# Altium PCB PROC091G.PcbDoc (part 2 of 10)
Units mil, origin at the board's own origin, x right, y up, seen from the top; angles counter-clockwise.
Board outline 4538.11 x 994.94 mil, 8 copper layers (Top Layer, GND1, Sig1, PWR1, PWR2, Sig2, GND2, Bottom Layer), stack 59.155 mil thick; 446 components, 329 nets, 5050 pads, 868 vias.
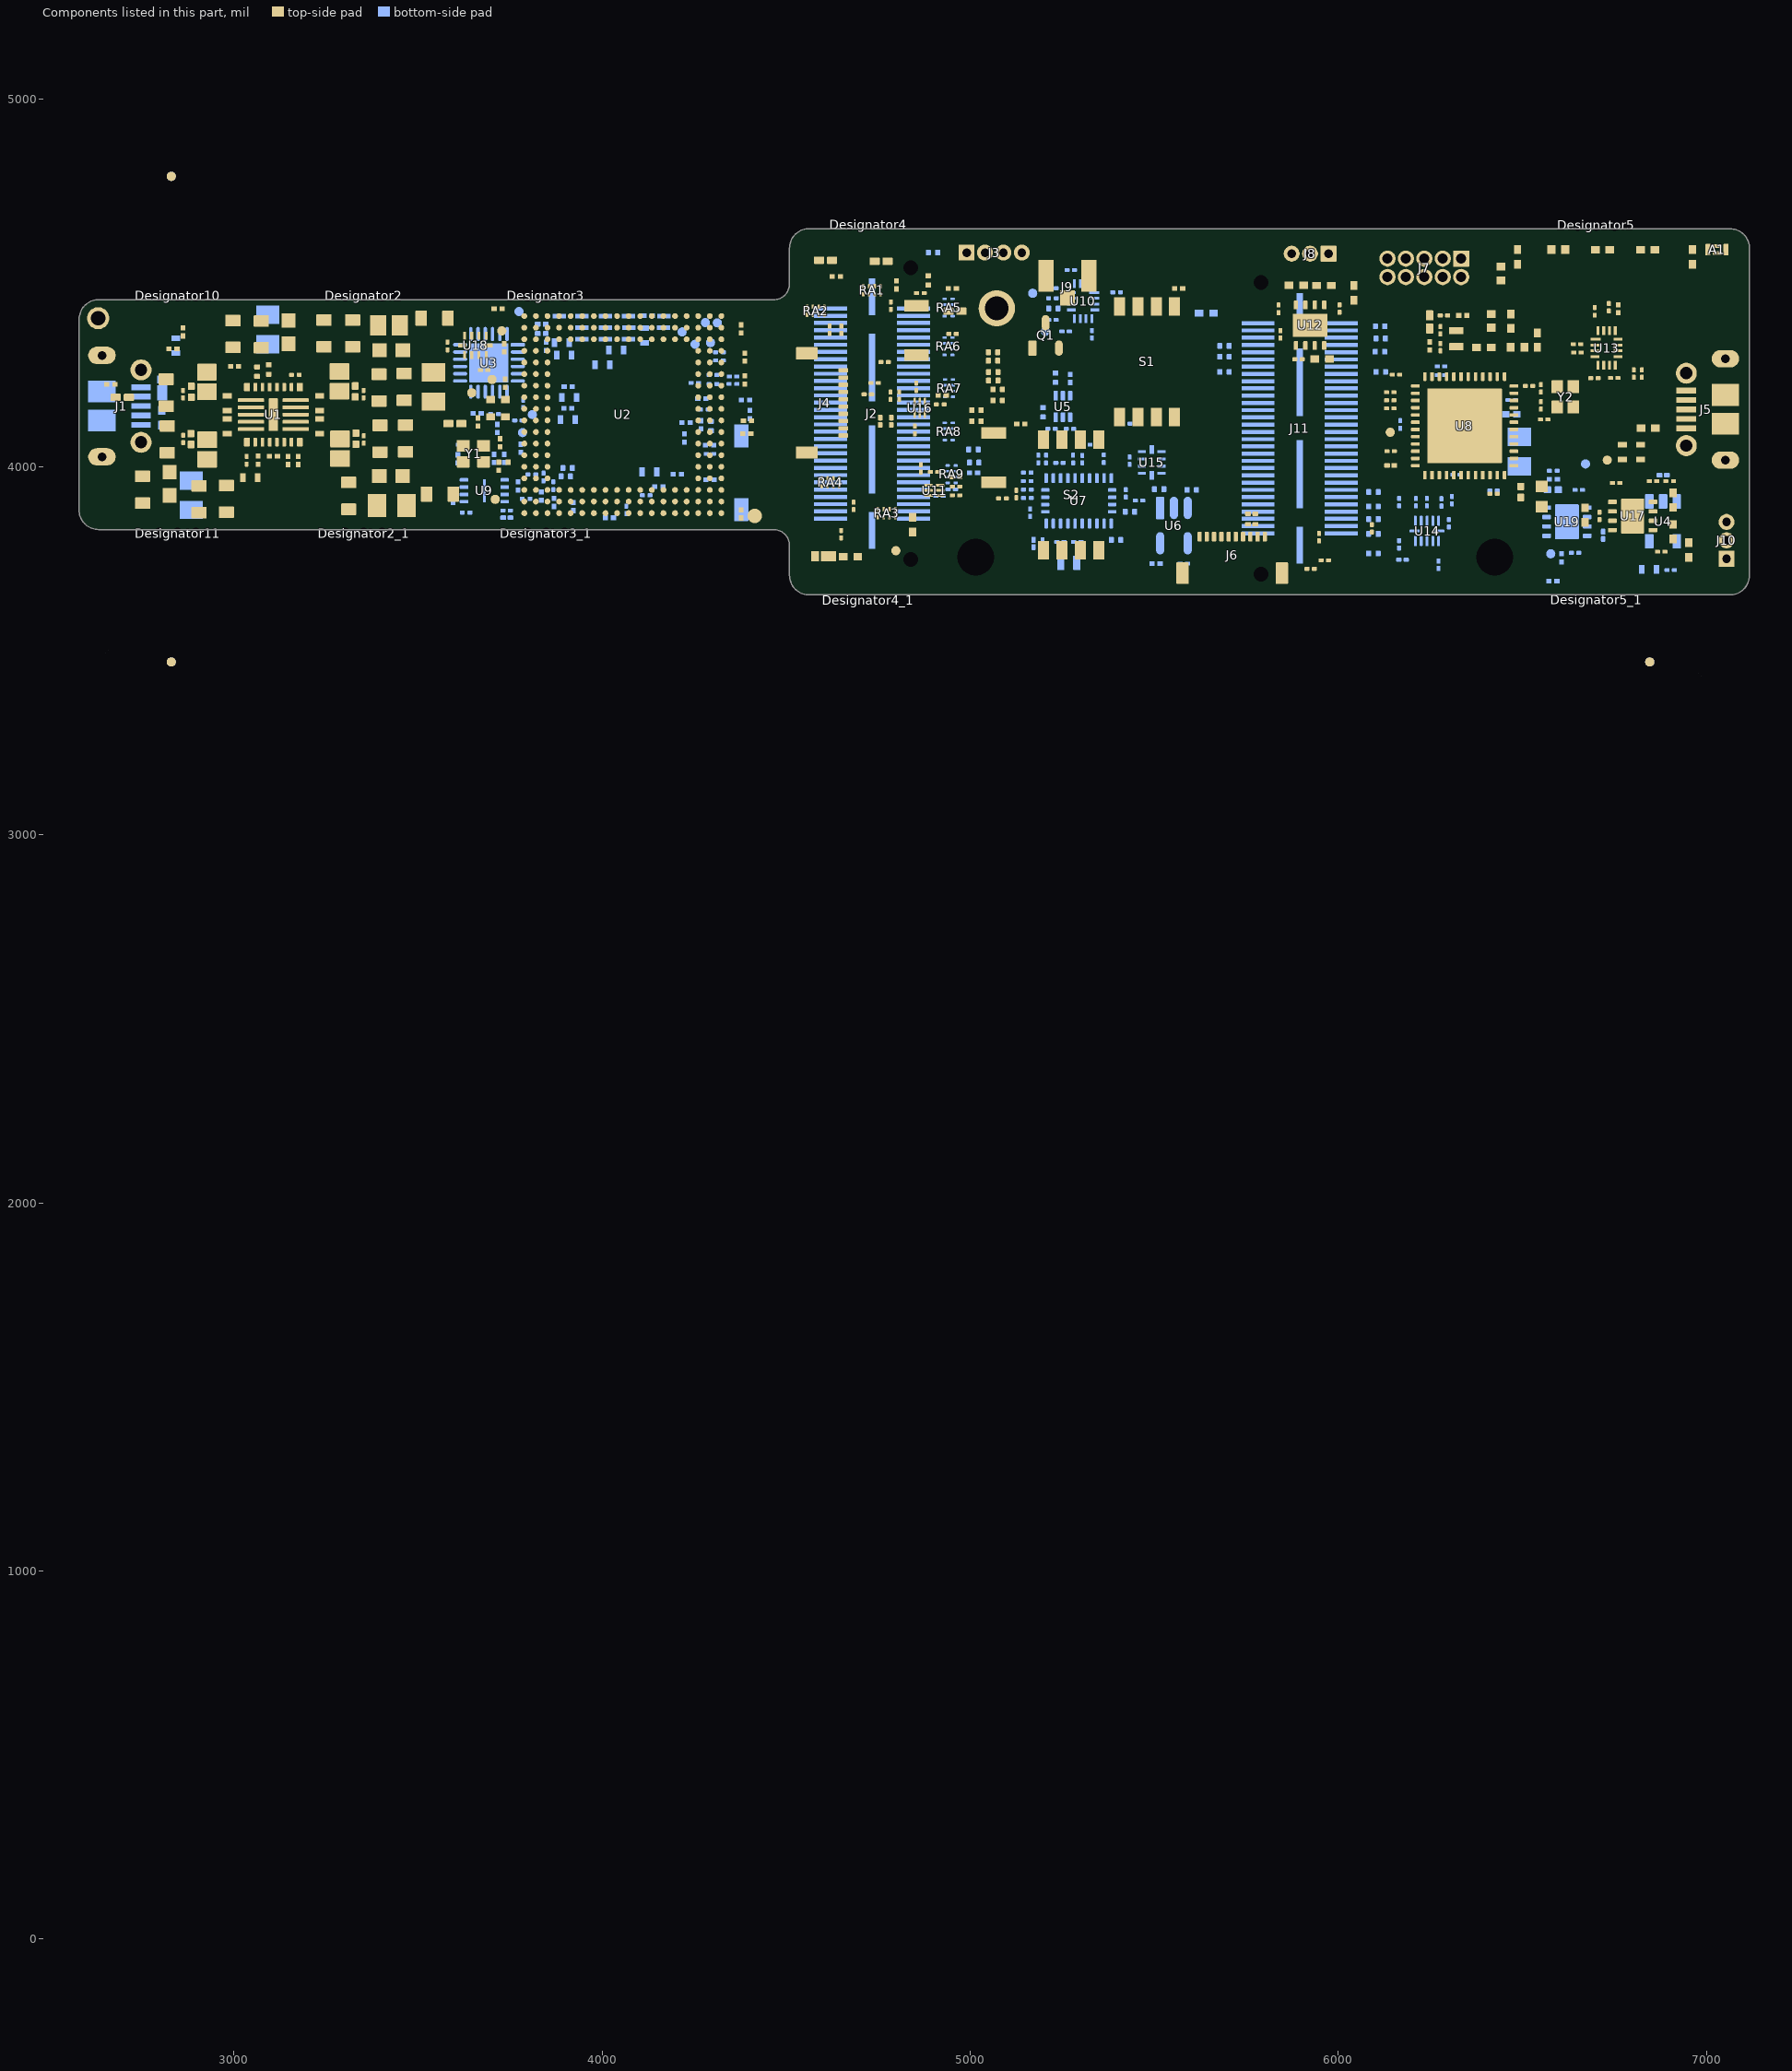
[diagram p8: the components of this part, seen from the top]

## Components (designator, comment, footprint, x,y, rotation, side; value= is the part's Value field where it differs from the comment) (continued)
R140 "AC0201FR-0720RL" FP-AC0201FR-0720RL_0201-IPC_C 4683.56,3893.44 r90 top
R141 "RC0201FR-074K99L" 0201L 6760.03,4429.26 r90 top value=4.99k
R142 "RC0201JR-070RL" "FP-RC0201JR-070RL_0201 (0603 Metric)-MFG" 5017.08,4123.69 r0 top
R143 "RC0201JR-070RL" "FP-RC0201JR-070RL_0201 (0603 Metric)-MFG" 5017.08,4153.69 r0 top
R144 "RC0201JR-070RL" "FP-RC0201JR-070RL_0201 (0603 Metric)-MFG" 5074.94,4180.12 r0 top
R145 "RC0201JR-070RL" "FP-RC0201JR-070RL_0201 (0603 Metric)-MFG" 5074.94,4210.12 r0 top
R146 "RC0201JR-070RL" "FP-RC0201JR-070RL_0201 (0603 Metric)-MFG" 5062.8,4234.19 r0 top
R147 "RC0201JR-070RL" "FP-RC0201JR-070RL_0201 (0603 Metric)-MFG" 5062.8,4257.19 r0 top
R148 "RC0201JR-070RL" "FP-RC0201JR-070RL_0201 (0603 Metric)-MFG" 5062.1,4288.03 r0 top
R149 "RC0201JR-070RL" "FP-RC0201JR-070RL_0201 (0603 Metric)-MFG" 5062.1,4311.03 r0 top
R150 "RC0201JR-070RL" "FP-RC0201JR-070RL_0201 (0603 Metric)-MFG" 6113.61,4381.76 r0 bottom
R151 "RC0201JR-070RL" "FP-RC0201JR-070RL_0201 (0603 Metric)-MFG" 6115.41,4348.48 r0 bottom
R152 "RC0201JR-070RL" "FP-RC0201JR-070RL_0201 (0603 Metric)-MFG" 5690.93,4328.4 r0 bottom
R153 "RC0201JR-070RL" "FP-RC0201JR-070RL_0201 (0603 Metric)-MFG" 6113.32,4312.59 r0 bottom
R154 "RC0201JR-070RL" "FP-RC0201JR-070RL_0201 (0603 Metric)-MFG" 5690.93,4298.93 r0 bottom
R155 "RC0201JR-070RL" "FP-RC0201JR-070RL_0201 (0603 Metric)-MFG" 6115.55,4257.57 r0 bottom
R157 "RC0201JR-070RL" "FP-RC0201JR-070RL_0201 (0603 Metric)-MFG" 5690.93,4257.72 r0 bottom
R158 "RC0201FR-0782K5L" 0201L 4228.2,4119.6 r0 bottom value=82.5k
R159 "RC0201JR-07750RL" 0201L 4223.5,4078.1 r270 bottom value=750
R160 "RC0201JR-070RL" "FP-RC0201JR-070RL_0201 (0603 METRIC)-IPC_C" 6280.34,3903.27 r90 bottom
R161 "RC0201JR-070RL" "FP-RC0201JR-070RL_0201 (0603 METRIC)-IPC_C" 6141.18,4158.46 r0 top
R166 "RC0201JR-070RL" "FP-RC0201JR-070RL_0201 (0603 METRIC)-IPC_C" 6240.62,3903.59 r90 bottom
R168 "RC0201JR-070RL" "FP-RC0201JR-070RL_0201 (0603 METRIC)-IPC_C" 6165.24,3903.57 r90 bottom
R170 "RC0201FR-0782K5L" 0201L 4154.35,3946.46 r180 bottom value=82.5k
R171 "RC0201JR-07750RL" 0201L 4204.44,3980.18 r0 bottom value=750
R172 "RC0201FR-0782K5L" 0201L 4401.11,4142.03 r90 bottom value=82.5k
R174 "RC0201FR-077K87L" 0201L 4269.1,4113.8 r90 bottom value=7.87k
R176 "RC0201FR-077K87L" 0201L 4389.6,4181.8 r0 bottom value=7.87k
R177 "RR0306P-103-D" FP-RR0306P-103-D_0201-IPC_C#1 4849.59,4099.95 r90 top
R178 "RR0306P-103-D" FP-RR0306P-103-D_0201-IPC_C#1 4918.69,4169.46 r180 top
R180 "ERJ-1GNF4701C" FP-ERJ-1GNF4701C_0201-IPC_C 6165.19,3789.15 r270 bottom
R181 "ERJ-1GNF4701C" FP-ERJ-1GNF4701C_0201-IPC_C 6091.28,3832.56 r90 top
R182 "RC0201JR-070RL" "FP-RC0201JR-070RL_0201 (0603 METRIC)-IPC_C" 4650.14,4371.83 r270 top locked
R183 "RC0201JR-070RL" "FP-RC0201JR-070RL_0201 (0603 METRIC)-IPC_C" 5947.68,3808.42 r270 top
R184 "RC0201JR-070RL" "FP-RC0201JR-070RL_0201 (0603 METRIC)-IPC_C" 5963.36,3745.98 r0 top
R185 "RC0201JR-070RL" "FP-RC0201JR-070RL_0201 (0603 METRIC)-IPC_C" 5925.33,3722.49 r180 top
R186 "RC0201JR-070RL" "FP-RC0201JR-070RL_0201 (0603 Metric)-MFG" 6095.54,3931.22 r0 bottom
R187 "RC0201JR-070RL" "FP-RC0201JR-070RL_0201 (0603 Metric)-MFG" 6095.54,3892.26 r0 bottom
R188 "RC0201JR-070RL" "FP-RC0201JR-070RL_0201 (0603 Metric)-MFG" 6095.54,3857.41 r0 bottom
R189 "RC0201JR-070RL" "FP-RC0201JR-070RL_0201 (0603 Metric)-MFG" 6095.54,3817.56 r0 bottom
R190 "RC0201JR-070RL" "FP-RC0201JR-070RL_0201 (0603 Metric)-MFG" 6095.54,3764.53 r0 bottom
RA1 "EXB-18VR000X" FP-EXB-18VR000X_0502-MFG 4733.17,4479.49 r180 top locked
RA2 "EXB-18VR000X" FP-EXB-18VR000X_0502-MFG 4580.6,4423.99 r180 top locked
RA3 "EXB-18VR000X" FP-EXB-18VR000X_0502-MFG 4772.94,3873.84 r0 top locked
RA4 "EXB-18VR000X" FP-EXB-18VR000X_0502-MFG 4620.57,3957.49 r0 top locked
RA5 "EXB-18VR000X" FP-EXB-18VR000X_0502-MFG 4941.51,4432.71 r90 bottom locked
RA6 "EXB-18VR000X" FP-EXB-18VR000X_0502-MFG 4941.09,4327.39 r90 bottom locked
RA7 "EXB-18VR000X" FP-EXB-18VR000X_0502-MFG 4942.52,4213.65 r90 bottom locked
RA8 "EXB-18VR000X" FP-EXB-18VR000X_0502-MFG 4941.86,4095.87 r90 bottom locked
RA9 "EXB-18VR000X" FP-EXB-18VR000X_0502-MFG 4949.85,3979.76 r90 bottom locked
S1 "218-4LPST" SW_218-4LPST 5480.37,4285.46 r90 top
S2 "218-4LPST" SW_218-4LPST 5274.37,3923.46 r90 top locked
S3 "CHS-01TA" FP-CHS-01TA_SMT_SW_5MM4_2MM5-MFG 4378.13,3983.7 r270 bottom
SW2 "B3U-1000P" SW_B3U-1000P 4854.16,4369.94 r270 top
SW3 "B3U-1000P" SW_B3U-1000P 5063.87,4024.39 r90 top
TP2 "TESTPOINT" TP_25MIL-SMT 3810.59,4141.77 r90 bottom
TP3 "TESTPOINT" TP_25MIL-SMT 3784,4092.76 r90 bottom
TP4 "TESTPOINT" TP_25MIL-SMT 6671.71,4007.65 r180 bottom
TP5 "TESTPOINT" TP_25MIL-SMT 3709.73,3911.44 r90 top
TP6 "TESTPOINT" TP_25MIL-SMT 4313,4390.94 r0 bottom
TP7 "TESTPOINT" TP_25MIL-SMT 4280.69,4391.59 r270 bottom
TP8 "TESTPOINT" TP_25MIL-SMT 4252.7,4332.6 r90 bottom
TP9 "TESTPOINT" TP_25MIL-SMT 4217.3,4366.19 r90 bottom
TP10 "TESTPOINT" TP_25MIL-SMT 6577.18,3763.46 r270 bottom
TP11 "TP_SM_1MM" TP_SM_1MM 4414.85,3866.34 r90 top
TP12 "TESTPOINT" TP_VIA_060RND040 2631.09,4403.54 r90 top
TP13 "TESTPOINT" TP_25MIL-SMT 4798.18,3771.83 r270 top
TP14 "TESTPOINT" TP_25MIL-SMT 4294.6,4337.1 r180 bottom
TP15 "TESTPOINT" TP_25MIL-SMT 6730.81,4018 r90 top
TP16 "TESTPOINT" TP_25MIL-SMT 6141.18,4093.46 r180 top
TP17 "TESTPOINT" TP_25MIL-SMT 3701,4237 r270 top
TP18 "TESTPOINT" TP_25MIL-SMT 3727.56,4369.01 r90 top
TP19 "TESTPOINT" TP_25MIL-SMT 3645.95,4200.94 r90 top
TP20 "4953" FP-4953_HDR1-MFG 5072.16,4430.47 r180 bottom locked
TP26 "TESTPOINT" TP_25MIL-SMT 3774.42,4421.63 r0 bottom
TP27 "TESTPOINT" TP_25MIL-SMT 5204,4368 r270 bottom
TP46 "TESTPOINT" TP_25MIL-SMT 5169.8,4471.3 r180 bottom
U1 "LP87524JRNFRQ1" RNF0026C 3107,4141.61 r270 top
U2 "XI6843ARQGALP" ALP0180A 4056.48,4141.61 r90 top
U3 "CP2105-F01-GMR" FP-CP2105-F01-GMR_QFN24-EP-IPC_A 3692.64,4282.2 r180 bottom
U4 "TPS79330DBVR" DBV0005A_N 6882.18,3851.63 r270 bottom
U5 "TMP112AQDRLRQ1" DRL0006A 5251.98,4163.77 r270 bottom locked
U6 "CAT24C08TDI-GT3" FP-CAT24C08TDI-GT3_TSOT-23-5-IPC_A 5553.54,3840.01 r270 bottom
U7 "BNO085" FP-BNO085_LGA28-MFG 5294.88,3907.22 r270 bottom
U8 "CC2642R1FRGZR" RGZ0048A 6343.38,4111.11 r270 top
U9 "MX25R1635FZUIH0" USON-8L 3680.29,3934.68 r0 bottom
U10 "TCA6408ARSVR" RSV0016A 5306.8,4449.73 r180 bottom
U11 "SN74LVC1G3157DSFR" DSF0006A 4902.7,3935.72 r0 top locked
U12 "TCAN1042HGVDRBRQ1" DRB0008F 5923.44,4384.46 r90 top
U13 "TS3A5018RSVR" RSV0016A 6728.94,4322.76 r0 top
U14 "TXB0104QRUTRQ1" RUT0012A 6241.04,3825.36 r90 bottom
U15 "TS5A23157RSER" RSE0010A 5493.28,4011.53 r180 bottom
U16 "SN74LVC1G11DSFR" DSF0006A-MFG 4863.37,4159.46 r90 top
U17 "TCAN1042HGVDRBRQ1" DRB0008F 6799.78,3866 r0 top
U18 "TS5A23157RSER" RSE0010A 3655.79,4329.59 r270 top
U19 "TPS2115ADRBR" DRB0008B 6621.18,3850.46 r0 bottom
Y1 "CX2016DB40000D0FLJCC" FP-CX2016DB40000D0FLJCC_SMT_2MM0_1MM6-MFG 3650.54,4035.03 r0 top
Y2 "CX2016DB48000C0WPLA2" FP-CX2016DB48000C0WPLA2_SMD4-MFG 6616.71,4189.85 r270 top
Y3 "ABS05W-32.768KHZ-D-2-T" FP-ABS05W-32.768KHZ-D-2-T_XTAL_SMT_1MM6_1MM0-MFG 6320.71,4347.93 r270 top
Y4 "ABS05W-32.768KHZ-D-2-T" FP-ABS05W-32.768KHZ-D-2-T_XTAL_SMT_1MM6_1MM0-MFG 5267.82,3738.88 r0 bottom
ZZ1 "This Assembly Note is for PCB labels only" AssemblyNoteLabel 2349.62,2814.36 r0 top
ZZ2 "These assemblies are ESD sensitive, ESD precautions shall be observed." AssemblyNote 2346.49,2738.89 r0 top
ZZ3 "These assemblies must be clean and free from flux and all contaminants. Use of no clean flux is not acceptable." AssemblyNote 2346.43,2653.5 r0 top
ZZ4 "These assemblies must comply with workmanship standards IPC-A-610 Class 2, unless otherwise specified." AssemblyNote 2343.34,2567.2 r0 top
ZZ5.1 "Cut the thermal pad(Part Number#GPVOUS-0.125-AC-0816) for the shape and size of the inner surface of the heatsink(Part Number#MCH054) and paste it on the inner surface of the heatsink;" AssemblyNote 2340.76,2492.7 r0 top
ZZ5.2 "Bring the heatsink onto the PCB bottom side (Opposite side of AOP device). Match the teeth in the heatsink with break-away area in the PCB and press the heatsink onto the PCB slightly so as thermal pad is spread all over the area" AssemblyNote 2343.41,2409 r0 top

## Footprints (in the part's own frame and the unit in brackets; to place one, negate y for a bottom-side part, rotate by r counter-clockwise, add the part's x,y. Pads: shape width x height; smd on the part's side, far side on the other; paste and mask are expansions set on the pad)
0201_033L [mm] "0201"
  rect 0.36x0.32 smd mask+0.048: 1(-0.28,0) 2(0.28,0)
  body extent -0.31,-0.16 0.31,0.16, height 0.33
0201L [mm] "Data from Kemet datasheet CC101_COM dated 7/28/11"
  rect 0.36x0.32 smd mask+0.048: 1(-0.28,0) 2(0.28,0)
  body extent -0.31,-0.16 0.31,0.16, height 0.26
0402_070 [mil] "SMD, 2-Leads, Body 1.2x0.7mm, Height 0.7mm"
  rect 15x24 smd: 1(-20,0) 2(20,0)
  body extent -24,-14 24,14, height 28
0402L [mm] "0402 from SM-752 data"
  rect 0.6x0.5 smd: 1(-0.5,0) 2(0.5,0)
  body extent -0.55,-0.3 0.55,0.3, height 0.6
0603 [mm] "0603 from SM-752 data"
  rect 1x0.95 smd: 1(-0.8,0) 2(0.8,0)
  silkscreen extent -1.52,-0.69 1.52,0.69, body extent -0.87,-0.47 0.87,0.47, height 1
0603L [mm] "0603 from SM-752 data"
  rect 0.8x0.85 smd: 1(-0.7,0) 2(0.7,0)
  silkscreen extent -0.07,-0.33 0.07,0.33, body extent -0.87,-0.47 0.87,0.47, height 1
0805_HV [mil] "0805 with 30mil clearance between pads"
  rect 50x63 smd: 1(-40,0) 2(40,0)
  silkscreen extent -74,-40 74,40, body extent -43,-29 43,29, height 57
0805L [mm] "0805 from SM-752 data"
  rect 1.1x1.4 smd: 1(-0.75,0) 2(0.75,0)
  body extent -1.1,-0.72 1.1,0.72, height 1.45
ALP0180A [mm] "BGA-180"
  round 0.4 smd: A1(-6.8,6.8) A2(-6,6.8) A3(-5.2,6.8) A4(-4.4,6.8) A5(-3.6,6.8) A6(-2.8,6.8) A7(-2,6.8) A8(-1.2,6.8) A9(-0.4,6.8) A10(0.4,6.8) A11(1.2,6.8) A12(2,6.8) A13(2.8,6.8) A14(3.6,6.8) A15(4.4,6.8) A16(5.2,6.8) A17(6,6.8) A18(6.8,6.8) B1(-6.8,6) B2(-6,6) B3(-5.2,6) B4(-4.4,6) B5(-3.6,6) B6(-2.8,6) B7(-2,6) B8(-1.2,6) B9(-0.4,6) B10(0.4,6) B11(1.2,6) B12(2,6) B13(2.8,6) B14(3.6,6) B15(4.4,6) B16(5.2,6) B17(6,6) B18(6.8,6) C1(-6.8,5.2) C2(-6,5.2) C3(-5.2,5.2) C4(-4.4,5.2) C5(-3.6,5.2) C6(-2.8,5.2) C7(-2,5.2) C8(-1.2,5.2) C9(-0.4,5.2) C10(0.4,5.2) C11(1.2,5.2) C12(2,5.2) C13(2.8,5.2) C14(3.6,5.2) C15(4.4,5.2) C16(5.2,5.2) C17(6,5.2) C18(6.8,5.2) D1(-6.8,4.4) D2(-6,4.4) D3(-5.2,4.4) D16(5.2,4.4) D17(6,4.4) D18(6.8,4.4) E1(-6.8,3.6) E2(-6,3.6) E3(-5.2,3.6) E16(5.2,3.6) E17(6,3.6) E18(6.8,3.6) F1(-6.8,2.8) F2(-6,2.8) F3(-5.2,2.8) F16(5.2,2.8) F17(6,2.8) F18(6.8,2.8) G1(-6.8,2) G2(-6,2) G3(-5.2,2) G16(5.2,2) G17(6,2) G18(6.8,2) H1(-6.8,1.2) H2(-6,1.2) H3(-5.2,1.2) H16(5.2,1.2) H17(6,1.2) H18(6.8,1.2) J1(-6.8,0.4) J2(-6,0.4) J3(-5.2,0.4) J16(5.2,0.4) J17(6,0.4) J18(6.8,0.4) K1(-6.8,-0.4) K2(-6,-0.4) K3(-5.2,-0.4) K16(5.2,-0.4) K17(6,-0.4) K18(6.8,-0.4) L1(-6.8,-1.2) L2(-6,-1.2) L3(-5.2,-1.2) L16(5.2,-1.2) L17(6,-1.2) L18(6.8,-1.2) M1(-6.8,-2) M2(-6,-2) M3(-5.2,-2) M16(5.2,-2) M17(6,-2) M18(6.8,-2) N1(-6.8,-2.8) N2(-6,-2.8) N3(-5.2,-2.8) N16(5.2,-2.8) N17(6,-2.8) N18(6.8,-2.8) P1(-6.8,-3.6) P2(-6,-3.6) P3(-5.2,-3.6) P16(5.2,-3.6) P17(6,-3.6) P18(6.8,-3.6) R1(-6.8,-4.4) R2(-6,-4.4) R3(-5.2,-4.4) R16(5.2,-4.4) R17(6,-4.4) R18(6.8,-4.4) T1(-6.8,-5.2) T2(-6,-5.2) T3(-5.2,-5.2) T4(-4.4,-5.2) T5(-3.6,-5.2) T6(-2.8,-5.2) T7(-2,-5.2) T8(-1.2,-5.2) T9(-0.4,-5.2) T10(0.4,-5.2) T11(1.2,-5.2) T12(2,-5.2) T13(2.8,-5.2) T14(3.6,-5.2) T15(4.4,-5.2) T16(5.2,-5.2) T17(6,-5.2) T18(6.8,-5.2) U1(-6.8,-6) U2(-6,-6) U3(-5.2,-6) U4(-4.4,-6) U5(-3.6,-6) U6(-2.8,-6) U7(-2,-6) U8(-1.2,-6) U9(-0.4,-6) U10(0.4,-6) U11(1.2,-6) U12(2,-6) U13(2.8,-6) U14(3.6,-6) U15(4.4,-6) U16(5.2,-6) U17(6,-6) U18(6.8,-6) V1(-6.8,-6.8) V2(-6,-6.8) V3(-5.2,-6.8) V4(-4.4,-6.8) V5(-3.6,-6.8) V6(-2.8,-6.8) V7(-2,-6.8) V8(-1.2,-6.8) V9(-0.4,-6.8) V10(0.4,-6.8) V11(1.2,-6.8) V12(2,-6.8) V13(2.8,-6.8) V14(3.6,-6.8) V15(4.4,-6.8) V16(5.2,-6.8) V17(6,-6.8) V18(6.8,-6.8)
  silkscreen extent -7.5,-7.5 7.5,7.5, body extent -7.5,-7.5 7.5,7.5, height 0.86
APHHS1005_Green [mm] "SMD, 2-Leads, Body 1x0.5mm"
  rrect20% 0.7x0.5 smd: 1(-0.45,0) 2(0.45,0)
  silkscreen extent -0.8,-0.65 1.2,0.65, body extent -0.5,-0.25 0.5,0.25, height 0.5
AssemblyNote [mil] "Assembly Note"
AssemblyNoteLabel [mil] "Assembly Note for PCB Labels"
BRAKE_WAY_HOLES1X2 [mil]
  round 27 hole 32 unplated mask+5.5: ""(-50,30.26) ""(0,30.26) ""(50,30.26)
CONN_105017-0001 [mm] "Molex Micro USB-B"
  rect 0.4x1.35 smd: 1(-1.3,1.35) 2(-0.65,1.35) 3(0,1.35) 4(0.65,1.35) 5(1.3,1.35)
  oval 1.2x1.9 hole 0.6 slot 1.3 at 90 deg: 6(-3.5,-1.35) 9(3.5,-1.35)
  rect 1.5x1.9 smd: 7(-1,-1.35) 8(1,-1.35)
  round 1.45 hole 0.85: 10(2.5,1.35) 11(-2.5,1.35)
  Top Layer region: -3.5,-0.4 -2.3,-0.4 -2.3,-2.3 -3.5,-2.3
  Top Layer region: 3.499,-2.3 2.299,-2.3 2.299,-0.4 3.499,-0.4
  silkscreen extent -4.1,-0.2 4.1,1.4, body extent -4.1,-3.93 4.1,1.5, height 2.72
CONN_UFL-R-SMT-1 [mm] "Hirose recommended land pattern http://www.hirose.co.jp/cataloge_hp/e32119372.pdf 2009.2"
  rect 1.05x1 smd paste-0.1 mask-0.1: 1(-1.525,0)
  rect 2x0.9 on Top Paste: 2(0,1.5) 3(0,-1.5)
  rect 2x0.9 on Top Solder: 2(0,1.5) 3(0,-1.5)
  rect 2.2x1.05 smd paste-2 mask-2: 2(0,1.475) 3(0,-1.475)
  Top Layer keep-out region: -0.8,-0.703 1.1,-0.703 1.1,0.697 -0.8,0.697
  silkscreen extent -1.7,-1.7 1.7,1.7, body extent -1.55,-1.5 1.55,1.5, height 1.27
DBV0005A_N [mm] "SOT23, 5-Leads, Body 2.9x1.6mm, Pitch 0.95mm, Lead Span 2.8mm, IPC Medium Density"
  rrect17% 1x0.6 smd: 1(-1.375,0.95) 2(-1.375,0) 3(-1.375,-0.95) 4(1.375,-0.95) 5(1.375,0.95)
  silkscreen extent -0.25,-1.55 0.25,1.55, body extent -1.42,-1.46 1.42,1.46, height 1.09
DRB0008B [mm] "SON, 8-Leads, Body 3x3mm, Pitch 0.65mm, Thermal Pad 2.4x1.65mm, TI Recommended"
  rrect33% 0.6x0.3 smd: 1(-1.4,0.975) 2(-1.4,0.325) 3(-1.4,-0.325) 4(-1.4,-0.975) 5(1.4,-0.975) 6(1.4,-0.325) 7(1.4,0.325) 8(1.4,0.975)
  rrect9% 1.47x1.06 on Bottom Paste: 9(0,-0.63) 9(0,0.63)
  rrect6% 1.65x2.4 smd paste-1.2: 9(0,0)
  silkscreen extent -1.73,-1.73 1.73,1.73, body extent -1.5,-1.5 1.5,1.5, height 0.96
DRB0008F [mm] "SON, 8-Leads, Body 3x3mm, Pitch 0.65mm, Thermal Pad 2.4x1.6mm, TI Recommended"
  rrect33% 0.6x0.3 smd: 1(-1.4,0.975) 2(-1.4,0.325) 3(-1.4,-0.325) 4(-1.4,-0.975) 5(1.4,-0.975) 6(1.4,-0.325) 7(1.4,0.325) 8(1.4,0.975)
  rrect9% 1.47x1.07 on Top Paste: 9(0,0.635) 9(0,-0.635)
  rrect6% 1.6x2.4 smd paste-1.2: 9(0,0)
  silkscreen extent -1.73,-1.73 1.73,1.73, body extent -1.5,-1.5 1.5,1.5, height 0.77
DRL0006A [mm] "SOTFL, 6-Flat Leads, Body 1.2x1.6x0.6mm, Pitch 0.5mm, TI recommended"
  rrect33% 0.67x0.3 smd: 1(-0.74,0.5) 2(-0.74,0) 3(-0.74,-0.5) 4(0.74,-0.5) 5(0.74,0) 6(0.74,0.5)
  silkscreen extent -0.9,-0.95 0.5,0.95, body extent -0.8,-0.8 0.8,0.8, height 0.61
DSF0006A [mm] "TI recommended land pattern"
  rrect59% 0.6x0.17 smd mask+0.045: 1(-0.4,0.35) 2(-0.4,0) 3(-0.4,-0.35) 4(0.4,-0.35) 5(0.4,0) 6(0.4,0.35)
  silkscreen extent -0.6,-0.63 0.6,0.63, body extent -0.5,-0.5 0.5,0.5, height 0.48
DSF0006A-MFG [mm]
  rrect59% 0.6x0.17 smd paste+0 mask+0: 1(-0.4,0.35) 2(-0.4,0) 3(-0.4,-0.35) 4(0.4,-0.35) 5(0.4,0) 6(0.4,0.35)
  silkscreen extent -1.14,-0.85 0.53,1.02, body extent -0.8,-0.63 0.8,0.63, height 0.25
DSN2_0603 [mm] "SMD, 2-Leads, Body 1.6x0.8mm"
  rect 0.52x0.7 smd: 1(-0.64,0)
  rect 1.05x0.7 smd: 2(0.275,0)
  silkscreen extent -1.4,-0.75 0.8,0.65, body extent -0.8,-0.4 0.8,0.4, height 0.31
Fiducial6.4-20 [mil]
  round 25 smd mask+26.87: 1(0,0)
  Top Layer keep-out circle w46.37: c0,0 r19.68
FP-250R05L120JV4T_0201-IPC_C [mm]
  rrect38% 0.363x0.263 smd paste+0 mask+0: 1(-0.25,0) 2(0.25,0)
  body extent -0.53,-0.27 0.53,0.26, height 0.25
FP-4953_HDR1-MFG [mm]
  round 2.5 hole 1.65 paste-1000 mask+0: 1(0,0)
  body extent -1.24,-0.25 1.24,0.25, height 9.16
FP-51441-1093_CONN_SMD_FFC-0 [mm]
  rrect33% 0.3x0.65 smd paste+0 mask+0: 1(-2.25,1.775) 2(-1.75,1.775) 3(-1.25,1.775) 4(-0.75,1.775) 5(-0.25,1.775) 6(0.25,1.775) 7(0.75,1.775) 8(1.25,1.775) 9(1.75,1.775) 10(2.25,1.775)
  rrect12% 0.85x1.5 smd paste+0 mask+0: 11(-3.425,-0.75) 12(3.425,-0.75)
  body extent -3.95,-1.9 3.95,2.2, height 0.25
FP-ABS05W-32.768KHZ-D-2-T_XTAL_SMT_1MM6_1MM0-MFG [mm]
  rrect20% 0.5x1 smd paste+0 mask+0: 1(-0.55,0) 2(0.55,0)
  body extent -0.95,-0.65 0.95,0.65, height 0.25
FP-AC0201FR-0720RL_0201-IPC_C [mil]
  rrect38% 13.94x10.34 smd paste+0 mask+0: 1(-10.01,0) 2(10.01,0)
  body extent -12,-6 12,6, height 10
FP-ANT016008LCS2442MA2_SMT_ANT-0 [mm]
  rrect29% 0.35x0.8 smd paste+0 mask+0.038: 1(-0.625,0) 4(0.625,0)
  rrect38% 0.6x0.26 smd paste+0 mask+0.038: 2-3(0,-0.235) 5-6(0,0.235)
  body extent -0.95,-0.55 0.95,0.55, height 0.25
FP-BNO085_LGA28-MFG [mm]
  rrect40% 0.675x0.25 smd paste+0 mask+0: 1(1.562,2.25) 6(-1.562,2.25) 7(-1.562,1.75) 8(-1.562,1.25) 9(-1.562,0.75) 10(-1.562,0.25) 11(-1.562,-0.25) 12(-1.562,-0.75) 13(-1.562,-1.25) 14(-1.562,-1.75) 15(-1.562,-2.25) 20(1.562,-2.25) 21(1.562,-1.75) 22(1.562,-1.25) 23(1.562,-0.75) 24(1.562,-0.25) 25(1.562,0.25) 26(1.562,0.75) 27(1.562,1.25) 28(1.562,1.75)
  rrect40% 0.25x0.575 smd paste+0 mask+0: 2(0.75,2.312) 3(0.25,2.312) 4(-0.25,2.312) 5(-0.75,2.312) 16(-0.75,-2.312) 17(-0.25,-2.312) 18(0.25,-2.312) 19(0.75,-2.312)
  body extent -1.9,-2.6 1.9,2.6, height 1.18
FP-BSS123-7-F_SOT23-IPC_C [mm]
  rrect18% 1.059x0.547 smd paste+0 mask+0: 1(-0.877,0.915)
  rrect100% 1.059x0.547 smd paste+0 mask+0: 2(-0.877,-0.915) 3(0.877,0)
  body extent -1.51,-1.55 1.51,1.55, height 0.25
FP-CAT24C08TDI-GT3_TSOT-23-5-IPC_A [mm]
  rrect18% 1.54x0.566 smd paste+0 mask+0: 1(-1.216,0.95)
  rrect100% 1.54x0.566 smd paste+0 mask+0: 2(-1.216,0) 3(-1.216,-0.95) 4(1.216,-0.95) 5(1.216,0.95)
  body extent -1.4,-1.45 1.4,1.45, height 1
FP-CGA4J1X7T0J226M125AC_0805-MFG [mm]
  rrect13% 0.8x1.05 smd paste+0 mask+0: 1(-0.925,0) 2(0.925,0)
  silkscreen extent -0.15,-0.77 0.15,0.77, body extent -1.43,-0.87 1.43,0.87, height 0.25
FP-CHS-01TA_SMT_SW_5MM4_2MM5-MFG [mm]
  rrect10% 1.6x1 smd paste+0 mask+0: 1(-2.54,0) 2(2.54,0)
  body extent -2.8,-1.25 2.8,1.25, height 2.5
FP-CL03A103KA3NNNC_0201-IPC_C [mil]
  rrect38% 13.94x10.34 smd paste+0 mask+0: 1(-10.01,0) 2(10.01,0)
  body extent -12,-6 12,6, height 15
FP-CL03A105MO3NRNH_0201-IPC_C [mil]
  rrect33% 15.83x11.94 smd paste+0 mask+0: 1(-9.87,0) 2(9.87,0)
  body extent -12,-6 12,6, height 15
FP-CL05A226MQ5N6J8_0402-IPC_C [mil]
  rrect21% 20.29x18.6 smd paste+0 mask+0: 1(-14.9,0) 2(14.9,0)
  body extent -29,-15 29,15, height 10
FP-CP2105-F01-GMR_QFN24-EP-IPC_A [mm]
  rrect42% 0.979x0.239 smd paste+0 mask+0: 1(-1.99,1.25)
  rrect100% 0.979x0.239 smd paste+0 mask+0: 2(-1.99,0.75) 3(-1.99,0.25) 4(-1.99,-0.25) 5(-1.99,-0.75) 6(-1.99,-1.25) 13(1.99,-1.25) 14(1.99,-0.75) 15(1.99,-0.25) 16(1.99,0.25) 17(1.99,0.75) 18(1.99,1.25)
  rrect100% 0.239x0.979 smd paste+0 mask+0: 7(-1.25,-1.99) 8(-0.75,-1.99) 9(-0.25,-1.99) 10(0.25,-1.99) 11(0.75,-1.99) 12(1.25,-1.99) 19(1.25,1.99) 20(0.75,1.99) 21(0.25,1.99) 22(-0.25,1.99) 23(-0.75,1.99) 24(-1.25,1.99)
  rrect4% 2.7x2.7 smd paste-1000 mask+0: 25(0,0)
  body extent -2,-2 2,2, height 0.8
FP-CRCW0402200RFKEDHP_0402-IPC_C [mil]
  rrect21% 20.29x18.6 smd paste+0 mask+0: 1(-14.9,0) 2(14.9,0)
  body extent -20,-10 20,10, height 16
FP-CX2016DB40000D0FLJCC_SMT_2MM0_1MM6-MFG [mm]
  rrect13% 0.9x0.8 smd paste+0 mask+0: 1(-0.7,-0.55) 2(0.7,-0.55) 3(0.7,0.55) 4(-0.7,0.55)
  body extent -1.25,-1.05 1.25,1.05, height 0.25
FP-CX2016DB48000C0WPLA2_SMD4-MFG [mm]
  rrect13% 0.9x0.8 smd paste+0 mask+0: 1(-0.7,-0.55) 2(0.7,-0.55) 3(0.7,0.55) 4(-0.7,0.55)
  silkscreen extent -1.85,-1.35 1.05,1.35, body extent -1.25,-1.05 1.25,1.05, height 0.25
FP-ERJ-1GNF4701C_0201-IPC_C [mil]
  rrect38% 13.94x10.34 smd paste+0 mask+0: 1(-10.01,0) 2(10.01,0)
  body extent -12,-6 12,6, height 10
FP-EXB-18VR000X_0502-MFG [mm]
  rrect57% 0.175x0.3 smd paste+0 mask+0: 1(-0.6,-0.275) 2(-0.2,-0.275) 3(0.2,-0.275) 4(0.6,-0.275) 5(0.6,0.275) 6(0.2,0.275) 7(-0.2,0.275) 8(-0.6,0.275)
  body extent -0.85,-0.53 0.85,0.53, height 0.25
"FP-GRM033R6YA104KE14D_0201 (0603 Metric)-IPC_C" [mil]
  rrect38% 13.94x10.34 smd paste+0 mask+0: 1(-10.01,0) 2(10.01,0)
  body extent -12,-6 12,6, height 13
"FP-GRM0335C1H8R0BA01D_0201 (0603 metric)-IPC_C" [mil]
  rrect38% 13.94x10.34 smd paste+0 mask+0: 1(-10.01,0) 2(10.01,0)
  body extent -21,-10 21,10, height 10
FP-GRPB052MWCN-RC_HDR10-MFG [mm]
  rrect9% 1.12x1.12 hole 0.7 paste-1000 mask+0: 1(-2.54,1.15)
  round 1.12 hole 0.7 paste-1000 mask+0: 2(-2.54,2.42) 3(-1.27,1.15) 4(-1.27,2.42) 5(0,1.15) 6(0,2.42) 7(1.27,1.15) 8(1.27,2.42) 9(2.54,1.15) 10(2.54,2.42)
  silkscreen extent -3.77,-0.7 3.42,1.17, body extent -3.18,-3.5 3.18,2.62, height 3.4
FP-M50-3930342_HDR3-MFG [mm]
  rrect9% 1.1x1.1 hole 0.6 paste-1000 mask+0: 1(-1.27,1)
  round 1.1 hole 0.6 paste-1000 mask+0: 2(0,1) 3(1.27,1)
  silkscreen extent -2.15,-0.6 2.15,2.09, body extent -1.91,-4.5 1.91,1.2, height 2.3
FP-M50-3930442_HDR4-RECOMMENDED_LAND_PATTERN [mm]
  rrect9% 1.1x1.1 hole 0.6 paste-1000 mask+0: 1(-1.905,1)
  round 1.1 hole 0.6 paste-1000 mask+0: 2(-0.635,1) 3(0.635,1) 4(1.905,1)
  body extent -2.54,-4.5 2.54,1.2, height 2.3
"FP-MCKK2012TR47M_0805 (2012 Metric)-IPC_C" [mil]
  rrect9% 45.45x53.39 smd paste+0 mask+0: 1(-26.61,0) 2(26.61,0)
  body extent -39,-25 39,25, height 39
"FP-RC0201JR-070RL_0201 (0603 Metric)-IPC_C" [mil]
  rrect38% 13.94x10.34 smd paste+0 mask+0: 1(-10.01,0) 2(10.01,0)
  body extent -12,-6 12,6, height 10
"FP-RC0201JR-070RL_0201 (0603 METRIC)-IPC_C" [mil]
  rrect38% 13.94x10.34 smd paste+0 mask+0: 1(-10.01,0) 2(10.01,0)
  body extent -12,-6 12,6, height 10
"FP-RC0201JR-070RL_0201 (0603 Metric)-MFG" [mm]
  rrect29% 0.35x0.4 smd paste+0 mask+0: 1(-0.325,0) 2(0.325,0)
  body extent -0.3,-0.15 0.3,0.15, height 0.26
"FP-RC0402FR-073R83L_0402 (1005 Metric)-IPC_C" [mil]
  rrect21% 20.29x18.6 smd paste+0 mask+0: 1(-14.9,0) 2(14.9,0)
  body extent -20,-10 20,10, height 16
FP-RR0306P-103-D_0201-IPC_C#1 [mil]
  rrect37% 13.31x10.73 smd paste+0 mask+0: 1(-10.52,0) 2(10.52,0)
  body extent -12,-6 12,6, height 10
FP-RR0306P-103-D_0201-IPC_C#2 [mil]
  rrect38% 13.94x10.34 smd paste+0 mask+0: 1(-10.52,0)
  rrect37% 13.31x10.73 smd paste+0 mask+0: 2(10.52,0)
  body extent -12,-6 12,6, height 10
"FP-TMK063CG391JT-F_0201 (0603 Metric)-IPC_C" [mil]
  rrect38% 13.94x10.34 smd paste+0 mask+0: 1(-10.01,0) 2(10.01,0)
  body extent -12,-6 12,6, height 13
IND_LQG15H [mm] "MuRata"
  rect 0.55x0.6 smd: 1(-0.475,0) 2(0.475,0)
  silkscreen extent -1.3,-0.3 -0.95,0.3, body extent -0.52,-0.27 0.52,0.27, height 0.55
MHNP_2-5 [mil]
  round 95 hole 100 unplated mask+5.5: ""(0,0)
  Keep-Out Layer circle w1: c0,0 r100
MHNP_M2_PANHEAD_PHILLIPS [mil]
  round 83 hole 88 unplated mask+5.5: ""(0,0)
  Keep-Out Layer circle w1: c0,0 r88
RGZ0048A [mm] "VQFN-48"
  rrect42% 0.6x0.24 smd: 1(-3.4,2.75) 2(-3.4,2.25) 3(-3.4,1.75) 4(-3.4,1.25) 5(-3.4,0.75) 6(-3.4,0.25) 7(-3.4,-0.25) 8(-3.4,-0.75) 9(-3.4,-1.25) 10(-3.4,-1.75) 11(-3.4,-2.25) 12(-3.4,-2.75) 25(3.4,-2.75) 26(3.4,-2.25) 27(3.4,-1.75) 28(3.4,-1.25) 29(3.4,-0.75) 30(3.4,-0.25) 31(3.4,0.25) 32(3.4,0.75) 33(3.4,1.25) 34(3.4,1.75) 35(3.4,2.25) 36(3.4,2.75)
  rrect42% 0.24x0.6 smd: 13(-2.75,-3.4) 14(-2.25,-3.4) 15(-1.75,-3.4) 16(-1.25,-3.4) 17(-0.75,-3.4) 18(-0.25,-3.4) 19(0.25,-3.4) 20(0.75,-3.4) 21(1.25,-3.4) 22(1.75,-3.4) 23(2.25,-3.4) 24(2.75,-3.4) 37(2.75,3.4) 38(2.25,3.4) 39(1.75,3.4) 40(1.25,3.4) 41(0.75,3.4) 42(0.25,3.4) 43(-0.25,3.4) 44(-0.75,3.4) 45(-1.25,3.4) 46(-1.75,3.4) 47(-2.25,3.4) 48(-2.75,3.4)
  rrect2% 5.15x5.15 smd paste-2.6: 49(0,0)
  body extent -3.5,-3.5 3.5,3.5, height 1
RNF0026C [mm] "QFN, 26-Leads, Body 4x4.5mm, Pitch 0.5mm"
  rrect25% 0.6x0.4 smd paste-0.3: 1(-1.9,1.825) 8(-1.9,-1.825) 14(1.9,-1.825) 21(1.9,1.825)
  rrect40% 0.6x0.25 smd paste+0: 2(-1.9,1.25) 3(-1.9,0.75) 4(-1.9,0.25) 5(-1.9,-0.25) 6(-1.9,-0.75) 7(-1.9,-1.25) 15(1.9,-1.25) 16(1.9,-0.75) 17(1.9,-0.25) 18(1.9,0.25) 19(1.9,0.75) 20(1.9,1.25)
  rrect40% 0.25x1.82 smd paste-1: 9(-1,-1.54) 10(-0.5,-1.54) 11(0,-1.54) 12(0.5,-1.54) 13(1,-1.54) 22(1,1.54) 23(0.5,1.54) 24(0,1.54) 25(-0.5,1.54) 26(-1,1.54)
  rrect15% 2.24x0.66 smd paste-1: 27(0,0)
  rrect33% 0.6x0.3 on Top Paste: ""(-1.9,1.775) ""(-1.9,-1.775) ""(1.9,1.775) ""(1.9,-1.775)
  rrect33% 0.3x0.825 on Top Paste: ""(-1.575,2.037) ""(-1.575,-2.037) ""(1.575,2.037) ""(1.575,-2.037)
  rrect40% 0.25x0.81 on Top Paste: ""(-1,2.045) ""(-1,1.035) ""(-1,-1.035) ""(-1,-2.045) ""(-0.5,2.045) ""(-0.5,1.035) ""(-0.5,-1.035) ""(-0.5,-2.045) ""(0,2.045) ""(0,1.035) ""(0,-1.035) ""(0,-2.045) ""(0.5,2.045) ""(0.5,1.035) ""(0.5,-1.035) ""(0.5,-2.045) ""(1,2.045) ""(1,1.035) ""(1,-1.035) ""(1,-2.045)
  rrect15% 0.98x0.66 on Top Paste: ""(-0.59,0) ""(0.59,0)
  Top Layer region: 1.425,1.675 1.425,2.4 1.429,2.419 1.44,2.435 1.456,2.446 1.475,2.45 1.475,2.45 1.725,2.45 1.744,2.446 1.76,2.435 1.771,2.419 1.775,2.4 1.775,2.4 1.775,1.675 1.771,1.656 1.76,1.64 1.744,1.629 1.725,1.625 1.725,1.625 1.475,1.625 1.456,1.629 1.44,1.64 1.429,1.656 1.425,1.675
  Top Layer region: 1.425,-2.4 1.425,-1.675 1.429,-1.656 1.44,-1.64 1.456,-1.629 1.475,-1.625 1.475,-1.625 1.725,-1.625 1.744,-1.629 1.76,-1.64 1.771,-1.656 1.775,-1.675 1.775,-1.675 1.775,-2.4 1.771,-2.419 1.76,-2.435 1.744,-2.446 1.725,-2.45 1.725,-2.45 1.475,-2.45 1.456,-2.446 1.44,-2.435 1.429,-2.419 1.425,-2.4
  Top Layer region: -1.775,1.675 -1.775,2.4 -1.771,2.419 -1.76,2.435 -1.744,2.446 -1.725,2.45 -1.725,2.45 -1.475,2.45 -1.456,2.446 -1.44,2.435 -1.429,2.419 -1.425,2.4 -1.425,2.4 -1.425,1.675 -1.429,1.656 -1.44,1.64 -1.456,1.629 -1.475,1.625 -1.475,1.625 -1.725,1.625 -1.744,1.629 -1.76,1.64 -1.771,1.656 -1.775,1.675
  Top Layer region: -1.775,-2.4 -1.775,-1.675 -1.771,-1.656 -1.76,-1.64 -1.744,-1.629 -1.725,-1.625 -1.725,-1.625 -1.475,-1.625 -1.456,-1.629 -1.44,-1.64 -1.429,-1.656 -1.425,-1.675 -1.425,-1.675 -1.425,-2.4 -1.429,-2.419 -1.44,-2.435 -1.456,-2.446 -1.475,-2.45 -1.475,-2.45 -1.725,-2.45 -1.744,-2.446 -1.76,-2.435 -1.771,-2.419 -1.775,-2.4
  silkscreen extent -2.45,-2.7 2.45,2.7, body extent -2,-2.25 2,2.25, height 0.9
RSE0010A [mm] "QFN, 10-Leads, Body 1.5x2mm, Pitch 0.5mm, TI Recommended"
  rect 0.55x0.2 smd: 1(-0.675,0.75) 2(-0.675,0.25) 3(-0.675,-0.25) 4(-0.675,-0.75) 6(0.675,-0.75) 7(0.675,-0.25) 8(0.675,0.25) 9(0.675,0.75)
  rect 0.3x0.6 smd: 5(0,-0.9) 10(0,0.9)
  silkscreen extent -1.07,-1.17 0.77,1.18, body extent -0.77,-1.02 0.78,1.03, height 0.61
RSV0016A [mm] "QFN, 16-Leads, Body 1.8x2.6mm, Pitch 0.4mm, TI Recommended"
  rect 0.7x0.2 smd: 1(-0.75,0.6)
  rect 0.6x0.2 smd: 2(-0.8,0.2) 3(-0.8,-0.2) 4(-0.8,-0.6) 9(0.8,-0.6) 10(0.8,-0.2) 11(0.8,0.2) 12(0.8,0.6)
  rect 0.2x0.6 smd: 5(-0.6,-1.2) 6(-0.2,-1.2) 7(0.2,-1.2) 8(0.6,-1.2) 13(0.6,1.2) 14(0.2,1.2) 15(-0.2,1.2) 16(-0.6,1.2)
  silkscreen extent -1.08,-1.33 1.08,1.45, body extent -0.92,-1.32 0.92,1.33, height 0.56
RUT0012A [mm] "QFN, 12-Leads, Body 1.7x2mm, Pitch 0.4mm, TI Recommended"
  rrect50% 0.7x0.2 smd: 1(-0.7,0.8) 2(-0.7,0.4) 3(-0.7,0) 4(-0.7,-0.4) 5(-0.7,-0.8) 7(0.7,-0.8) 8(0.7,-0.4) 9(0.7,0) 10(0.7,0.4) 11(0.7,0.8)
  rrect50% 0.2x0.7 smd: 6(0,-0.85) 12(0,0.85)
  silkscreen extent -0.9,-1.2 0.9,1.2, body extent -0.85,-1 0.85,1, height 0.55
Samtec_QSH-030-01-X-D-A [mm] "Receptacle, 0.5 mm, 30x2, TH"
  rect 2.27x0.279 smd: 1(-2.865,7.25) 2(2.865,7.25) 3(-2.865,6.75) 4(2.865,6.75) 5(-2.865,6.25) 6(2.865,6.25) 7(-2.865,5.75) 8(2.865,5.75) 9(-2.865,5.25) 10(2.865,5.25) 11(-2.865,4.75) 12(2.865,4.75) 13(-2.865,4.25) 14(2.865,4.25) 15(-2.865,3.75) 16(2.865,3.75) 17(-2.865,3.25) 18(2.865,3.25) 19(-2.865,2.75) 20(2.865,2.75) 21(-2.865,2.25) 22(2.865,2.25) 23(-2.865,1.75) 24(2.865,1.75) 25(-2.865,1.25) 26(2.865,1.25) 27(-2.865,0.75) 28(2.865,0.75) 29(-2.865,0.25) 30(2.865,0.25) 31(-2.865,-0.25) 32(2.865,-0.25) 33(-2.865,-0.75) 34(2.865,-0.75) 35(-2.865,-1.25) 36(2.865,-1.25) 37(-2.865,-1.75) 38(2.865,-1.75) 39(-2.865,-2.25) 40(2.865,-2.25) 41(-2.865,-2.75) 42(2.865,-2.75) 43(-2.865,-3.25) 44(2.865,-3.25) 45(-2.865,-3.75) 46(2.865,-3.75) 47(-2.865,-4.25) 48(2.865,-4.25) 49(-2.865,-4.75) 50(2.865,-4.75) 51(-2.865,-5.25) 52(2.865,-5.25) 53(-2.865,-5.75) 54(2.865,-5.75) 55(-2.865,-6.25) 56(2.865,-6.25) 57(-2.865,-6.75) 58(2.865,-6.75) 59(-2.865,-7.25) 60(2.865,-7.25)
  round 0 hole 1.02 unplated: MH1(2.67,10.065) MH2(2.67,-10.065)
  rect 0.43x2.54 smd: MP1(0,8.065) MP4(0,-8.065)
  rect 0.43x4.7 smd: MP2(0,3.175) MP3(0,-3.175)
  silkscreen extent -3.9,-10.66 3.62,10.66, body extent -3.75,-10.64 3.75,10.67, height 3.25
SW_218-4LPST [mil] "CTS Components"
  rect 50x30 smd: 1(-150,75) 2(-150,25) 3(-150,-25) 4(-150,-75) 5(150,-75) 6(150,-25) 7(150,25) 8(150,75)
  silkscreen extent -114,-123 114,123, body extent -166,-123 166,123, height 104
SW_B3U-1000P [mm] "OMRON"
  rect 0.8x1.7 smd: 1(-1.7,0) 2(1.7,0)
  silkscreen extent -1.5,-1.25 1.5,1.25, body extent -1.5,-1.25 1.5,1.25, height 1.75
TP_25MIL-SMT [mil]
  round 25 smd mask-2.5: 1(0,0)
TP_SM_1MM [mm] "1mm Test Point, SMT"
  round 1 smd paste-0.5: 1(0,0)
TP_VIA_060RND040 [mil] "TP_VIA_060RND040"
  round 60 hole 40: 1(0,0)
USON-8L [mm] "SON, 8-Leads, Body 3x2mm, Pitch 0.5mm"
  rrect40% 0.6x0.25 smd: 1(-1.4,0.75) 2(-1.4,0.25) 3(-1.4,-0.25) 4(-1.4,-0.75) 5(1.4,-0.75) 6(1.4,-0.25) 7(1.4,0.25) 8(1.4,0.75)
  rrect50% 0.2x1.6 smd: 9(0,0)
  silkscreen extent -1.55,-1.17 0.65,1.17, body extent -1.55,-1.05 1.55,1.05, height 0.6

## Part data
A1: library part CMP-0087189-1, "RF ANT 2.4GHZ CHIP SOLDER SMD", Manufacturer="TDK Corporation"
C1 C4 C7 C42 C50 C51 C52 C53 C55 C59 C62 C65 C70 C73 C78 C82 C122: library part CMP-0006339-4, "CAP, CERM, 10 uF, 10 V, +/- 20%, X5R, 0402", Cap_Case=0402, Manufacturer="Samsung Electro-Mechanics", TempCo=X5R, Tolerance_%=20%, Value1=Unknown, Value2=10V, ValueDisplayed=10uF
C2 C3 C6 C9 C10 C12 C13 C25 C26 C27 C35 C36 C37 C40 C43 C72 C86 C91 C92 C101 C105 C107 C108 C109 C114 C117 C118 C119 C120 C123 C126 C127 C128 C130: library part CMP-0086440-1, "Cap Ceramic 0.1uF 35V X5R 10% Pad SMD 0201 85C T/R", Manufacturer="Murata Electronics North America", TempCo=15%, Tolerance_%=10%
C5 C11 C15 C16 C24 C100 C115 C116 C129: library part CMP-0086446-1, "1µF ±20% 16V Ceramic Capacitor X5R 0201", Manufacturer="Samsung Electro-Mechanics", TempCo=15%, Tolerance_%=20%
C8 C125: library part CMP-0086445-1, "CAP CER 10000PF 25V X5R 0201", Manufacturer="Samsung Electro-Mechanics America, Inc", TempCo=15%, Tolerance_%=10%
C14 C71: library part CMP-0080076-1, "CAP, CERM, 4.7 pF, 50 V,+/- 3%, C0G/NP0, 0201", Cap_Case=0201, Manufacturer=MuRata, Supplier Part Number 1=490-11332-1-ND, TempCo=C0G/NP0, Tolerance_%=3%, Value2=50V, ValueDisplayed=4.7pF
C17 C18: library part CMP-0086441-1, "Cap Ceramic 8pF 50V C0G 0.1pF SMD 0201 125°C Paper T/R", Manufacturer=Murata, TempCo=30ppm/°C
C19 C20 C38 C39: library part CMP-0087190-1, "CAP CER 12PF 25V C0G/NP0 0201", Manufacturer="Johanson Technology Inc.", TempCo=30ppm/°C, Tolerance_%=5%
C21 C93: library part CMP-0006345-2, "CAP, CERM, 12 pF, 50 V, +/- 5%, C0G/NP0, 0402", Cap_Case=0402, Manufacturer="Samsung Electro-Mechanics", Supplier Part Number 1=1276-1178-1-ND, TempCo=C0G/NP0, Tolerance_%=5%, Value1=Unknown, Value2=50V, ValueDisplayed=12pF
C22 C23 C41: library part CMP-0085178-1, "CAP, CERM, 1 pF, 50 V,+/- 25%, C0G/NP0, AEC-Q200 Grade 1, 0402", Cap_Case=0402, Manufacturer=MuRata, TempCo=C0G/NP0, Tolerance_%=25%, Value2=50V, ValueDisplayed=1pF
C28 C29: library part CMP-0089043-3, "CAP CER 22UF 6.3V X5R 0402", Manufacturer="Samsung Electro-Mechanics", TempCo=15%, Tolerance_%=20%, ValueDisplayed=22uF
C30 C56 C57 C58 C60 C61 C63 C64 C66 C67 C68 C75 C76 C80 C81 C84 C85 C87 C88 C94 C95 C96 C97 C98: library part CMP-0009781-1, "CAP, CERM, 0.22 uF, 10 V, +/- 20%, X5R, 0201", Cap_Case=0201, Manufacturer="Taiyo Yuden", Supplier Part Number 1=587-2483-1-ND, TempCo=X5R, Tolerance_%=20%, Value1=Unknown, Value2=10V, ValueDisplayed=0.22uF
C31 C32 C33 C34: library part CMP-0086438-1, "CAP CER 390PF 25V C0G/NP0 0201", Manufacturer="Taiyo Yuden", TempCo=30ppm/°C, Tolerance_%=5%
C44 C45 C46 C47 C111 C112 C113 C121 C131 C133 C135 C137 C138 C139 C140 C141: library part CMP-0091983-1, "22µF ±20% 6.3V Ceramic Capacitor X7T 0805 (2012 Metric)", Digikey Part Number=445-CGA4J1X7T0J226M125ACCT-ND, Manufacturer=TDK, Mouser Part Number=810-CGA4J1X7T0J226M1, Operating Temperature Range="-55°C to +125°C", TempCo=+22/-33%, Temperature Characteristic=X7T, Tolerance_%=20%, ValueDisplayed=22uF
C69: library part CMP-0009718-2, "CAP, CERM, 0.047 uF, 16 V, +/- 10%, X5R, 0201", Cap_Case=0201, Manufacturer=MuRata, Supplier Part Number 1=490-7227-1-ND, TempCo=X5R, Tolerance_%=10%, Value1=Unknown, Value2=16V, ValueDisplayed=0.047uF
C74 C79 C83 C102 C103: library part CMP-0009657-3, "CAP, CERM, 2.2 uF, 6.3 V, +/- 20%, X5R, 0201", Cap_Case=0201, Manufacturer="Samsung Electro-Mechanics", TempCo=X5R, Tolerance_%=20%, Value1=Unknown, Value2=6.3V, ValueDisplayed=2.2uF
C89 C90: library part CMP-0081763-1, "CAP, CERM, 1 µF, 6.3 V,+/- 10%, X6S, 0402", Cap_Case=0402, Manufacturer=TDK, Supplier Part Number 1=445-13189-1-ND, TempCo=X6S, Tolerance_%=10%, Value2=6.3V, ValueDisplayed=1µF
C99 C104: library part CMP-0086306-1, "CAP, CERM, 1.8 pF, 50 V,+/- 6%, C0G/NP0, 0402", Cap_Case=0402, Manufacturer=MuRata, TempCo=C0G/NP0, Tolerance_%=6%, Value2=50V, ValueDisplayed=1.8pF
C106 C110: library part CMP-0006692-2, "CAP, CERM, 4700 pF, 50 V, +/- 10%, X7R, 0402", Cap_Case=0402, Manufacturer=MuRata, Supplier Part Number 1=490-1308-1-ND, TempCo=X7R, Tolerance_%=10%, Value1=Unknown, Value2=50V, ValueDisplayed=4700pF
C124 C132 C134 C136: library part CMP-0008017-1, "CAP, CERM, 10 uF, 10 V, +/- 10%, X7R, 0805", Cap_Case=0805, Manufacturer=MuRata, Supplier Part Number 1=490-10674-1-ND, TempCo=X7R, Tolerance_%=10%, Value1=Unknown, Value2=10V, ValueDisplayed=10uF
D1 D2: library part CMP-0028829-2, "Diode, Schottky, 30 V, 2 A, 2-XFDFN", Manufacturer="ON Semiconductor", Value1=2A, Value2=0.48V
FID1 FID2 FID3 FID4 FID5 FID6: library part CMP-0077181-1, "Fiducial mark.  There is nothing to buy or mount.", Manufacturer=N/A
FL2 FL3 FL4 FL11 FL12 FL14 FL22: library part CMP-0078934-1, "Inductor, Ferrite Bead, Ferrite, 2.2 A, 0.035 ohm, AEC-Q200 Grade 1, SMD", Manufacturer=MuRata, Supplier Part Number 1=490-16506-1-ND, Value1="0.035 ohm", Value2=2.2A
J1 J5: library part CMP-0055293-1, "Connector, Receptacle, Micro-USB Type B, R/A, Bottom Mount SMT", Manufacturer=Molex, Supplier Part Number 1=WM1399CT-ND
J2 J11: library part CMP-0075524-1, "Receptacle, 0.5 mm, 30x2, Gold, TH", Color=Black, Manufacturer=Samtec, Supplier Part Number 1=SAM8180-ND
J3: library part CMP-0087187-1, "CONN HDR 1.27MM R/A AU 4POS", Current_A=1A, Manufacturer="Harwin Inc."
J4 J6: library part CMP-0086453-1, "Easy-On™ Type FFC/FPC Connector, Right-Angle, Surface Mount, ZIF, Bottom Contact Style, 1.10mm Mated Height, 10 Circuits", Manufacturer=Molex
J7: library part CMP-0087786-1, "CONN HEADER R/A 10POS 1.27MM", Current_A=1A, Manufacturer=Sullins
J8 J10: library part CMP-0087785-1, "CONN HEADER R/A 3POS 1.27MM", Current_A=1A, Manufacturer=Harwin
J9: library part CMP-0075320-1, "Receptacle, Ultra Miniature Coaxial, Male Pin, 50 ohm, SMT", Color=Beige, Manufacturer="Hirose Electric Co. Ltd.", Supplier Part Number 1=H122041-ND
L1 L6: library part CMP-0058626-1, "Inductor, Multilayer, Air Core, 2.4 nH, 0.3 A, 0.15 ohm, SMD", Manufacturer=MuRata, Supplier Part Number 1=LQG15HS2N4S02D-ND, Value1="0.15 ohm", Value2=0.3A, ValueDisplayed=2.4nH
L2 L3 L4 L5: library part CMP-0087178-1, "FIXED IND 470NH 4.5A 39 MOHM SMD", Manufacturer="Taiyo Yuden"
L7: library part CMP-0062727-1, "Inductor, Multilayer, Ferrite, 6.8 uH, 0.11 A, 0.25 ohm, SMD", Manufacturer=TDK, Supplier Part Number 1=445-6761-1-ND, Value1="0.25 ohm", Value2=0.11A, ValueDisplayed=6.8uH
L8: library part CMP-0003349-2, "Ferrite Bead, 1500 ohm @ 100 MHz, 0.5 A, 0603", Manufacturer=MuRata, Supplier Part Number 1=490-5216-1-ND, Value1="0.5 ohm", Value2=0.5A, ValueDisplayed="1500 ohm"
L9 L10: library part CMP-0058624-1, "Inductor, Multilayer, Air Core, 2 nH, 0.3 A, 0.1 ohm, SMD", Manufacturer=MuRata, Supplier Part Number 1=490-6569-1-ND, Value1="0.1 ohm", Value2=0.3A, ValueDisplayed=2nH
L11 L12 L13 L14: library part CMP-0077879-1, "Ferrite Bead, 120 ohm @ 100 MHz, 1.9 A, 0603", Manufacturer=MuRata, Supplier Part Number 1=490-13261-1-ND, Value1="0.04 ohm", Value2=1.9A, ValueDisplayed="120 ohm"
L15: library part CMP-0003363-1, "Ferrite Bead, 220 ohm @ 100 MHz, 2 A, 0805", Manufacturer=MuRata, Supplier Part Number 1=490-1054-1-ND, Value1="0.045 ohm", Value2=2A, ValueDisplayed="220 ohm"
LD1 LD2 LD3 LD4 LD5 LD6: library part CMP-0067682-2, "LED, Green, SMD", Color=Green, Manufacturer=Kingbright, Power_TotalModule=75mW, Value1=0.075W, Value2=2.1V
Q1: library part CMP-0087176-1, "MOSFET N-CH 100V 170MA SOT23-3", Manufacturer="Diodes Incorporated"
R1 R3 R7 R8 R18 R19 R20 R21 R22 R23 R35 R36 R43 R44 R45 R59 R65 R77 R78 R80 R81 R82 R83 R84 R85 R93 R94 R95 R96 R98 R104 R110 R118 R122 R124 R125 R134 R177 R178: library part CMP-0088002-1, "10 kOhms ±0.5% 0.05W, 1/20W Chip Resistor 0201 (0603 Metric)  Thin Film", Manufacturer=Susumu, Power_W=50mW, TempCo=25ppm/°C, Tolerance_%=0.5%
R2 R12 R14 R28 R30 R31 R32 R41 R51 R57 R58 R60 R61 R62 R66 R67 R68 R70 R71 R72 R73 R74 R76 R86 R87 R90 R91 R97 R99 R100 R101 R102 R103 R105 R106 R109 R112 R113 R115 R116 R120 R121 R123 R127 R128 R129 R131 R136 R139 R142 R143 R144 R145 R146 R147 R148 R149 R150 R151 R152 R153 R154 R155 R157 R160 R161 R166 R168 R182 R183 R184 R185 R186 R187 R188 R189 R190: library part CMP-0086442-2, "RES SMD 0 OHM JUMPER 1/20W 0201", Manufacturer=Yageo, Power_W=50mW, TempCo=200ppm/°C, Tolerance_%=5%
R4 R5 R9 R29 R37 R89 R92: library part CMP-0027261-3, "RES, 100 k, 1%, 0.05 W, 0201", Manufacturer=Vishay-Dale, Power_W=50mW, Supplier Part Number 1=541-100KAABCT-ND, TempCo="100 ppm/C", Tolerance_%=1%, Value2=0.05W, Value_Code=100k
R6 R46 R47 R48 R49: library part CMP-0027275-3, "RES, 33.2, 1%, 0.05 W, 0201", Manufacturer=Vishay-Dale, Power_W=50mW, Supplier Part Number 1=541-33.2ABCT-ND, TempCo="200 ppm/C", Tolerance_%=1%, Value2=0.05W, Value_Code=33R2, ValueDisplayed=33.2
R10 R11 R88 R130 R132 R133 R135 R137 R138 R140: library part CMP-0087185-1, "RES SMD 20 OHM 1% 1/20W 0201", Manufacturer=Yageo, Power_W=50mW, TempCo=200ppm/°C, Tolerance_%=1%
R13 R15 R17 R42 R111: library part CMP-0027072-1, "RES, 220, 5%, 0.05 W, 0201", Manufacturer="Yageo America", Power_W=50mW, Supplier Part Number 1=311-220NCT-ND, TempCo="200 ppm/C", Tolerance_%=5%, Value2=0.05W, Value_Code=220R, ValueDisplayed=220
R16 R174 R176: library part CMP-0027880-1, "RES, 7.87 k, 1%, 0.05 W, 0201", Manufacturer="Yageo America", Power_W=50mW, Supplier Part Number 1=YAG2807CT-ND, TempCo="200 ppm/C", Tolerance_%=1%, Value2=0.05W, Value_Code=7k87, ValueDisplayed=7.87k
R24: library part CMP-0087183-1, "RES SMD 200 OHM 1% 1/5W 0402", Manufacturer="Vishay Dale", Power_W=200mW, TempCo=100ppm/°C, Tolerance_%=1%
R25 R26 R33 R34 R38 R40 R64 R69 R141: library part CMP-0027745-1, "RES, 4.99 k, 1%, 0.05 W, 0201", Manufacturer="Yageo America", Power_W=50mW, Supplier Part Number 1=YAG2712CT-ND, TempCo="200 ppm/C", Tolerance_%=1%, Value2=0.05W, Value_Code=4k99, ValueDisplayed=4.99k
R27 R39 R107 R108: library part CMP-0027137-1, "RES, 510, 5%, 0.05 W, 0201", Manufacturer="Yageo America", Power_W=50mW, Supplier Part Number 1=YAG2907CT-ND, TempCo="200 ppm/C", Tolerance_%=5%, Value2=0.05W, Value_Code=510R, ValueDisplayed=510
R50 R75: library part CMP-0027052-1, "RES, 1.0 k, 5%, 0.05 W, 0201", Manufacturer="Yageo America", Power_W=50mW, Supplier Part Number 1=311-1KNCT-ND, TempCo="200 ppm/C", Tolerance_%=5%, Value2=0.05W, Value_Code=1k00, ValueDisplayed=1.0k
R52: library part CMP-0027452-1, "RES, 1.96 k, 1%, 0.05 W, 0201", Manufacturer="Yageo America", Power_W=50mW, Supplier Part Number 1=YAG2494CT-ND, TempCo="200 ppm/C", Tolerance_%=1%, Value2=0.05W, Value_Code=1k96, ValueDisplayed=1.96k
R53 R54 R55 R56: library part CMP-0086444-2, "RES Thick Film SMD 3.83O 1% 1/16W 0402 200ppm/°C", Manufacturer=Yageo, Power_W=63mW, TempCo=200ppm/°C, Tolerance_%=1%
R79 R180 R181: library part CMP-0087184-1, "RESISTOR, 0201, 0.05W, 1%, 4K7", Manufacturer="Panasonic Electronic Components", Power_W=50mW, TempCo=200ppm/°C, Tolerance_%=1%
R114 R117 R119 R126: library part CMP-0026491-2, "RES, 61.9, 1%, 0.063 W, AEC-Q200 Grade 0, 0402", Manufacturer=Vishay-Dale, Power_W=63mW, Supplier Part Number 1=541-61.9LCT-ND, TempCo="100 ppm/C", Tolerance_%=1%, Value2=0.063W, Value_Code=61R9, ValueDisplayed=61.9
R158 R170 R172: library part CMP-0027891-1, "RES, 82.5 k, 1%, 0.05 W, 0201", Manufacturer="Yageo America", Power_W=50mW, Supplier Part Number 1=YAG2815CT-ND, TempCo="200 ppm/C", Tolerance_%=1%, Value2=0.05W, Value_Code=82k5, ValueDisplayed=82.5k
R159 R171: library part CMP-0027165-1, "RES, 750, 5%, 0.05 W, 0201", Manufacturer="Yageo America", Power_W=50mW, Supplier Part Number 1=YAG2927CT-ND, TempCo="200 ppm/C", Tolerance_%=5%, Value2=0.05W, Value_Code=750R, ValueDisplayed=750
RA1 RA2 RA3 RA4 RA5 RA6 RA7 RA8 RA9: library part CMP-0087186-1, "RES ARRAY 4 RES ZERO OHM 0502", Manufacturer="Panasonic Electronic Components", Power_W=100mW, TempCo=-200/+600ppm/°C, Tolerance_%=5%
S1 S2: library part CMP-0002128-2, "Switch, Slide, SPST 4 poles, SMT", CurrentRating_mA=25A, Manufacturer="CTS Electrocomponents", Supplier Part Number 1=CT2184LPST-ND
S3: library part CMP-0087181-1, "SWITCH SLIDE DIP SPST 100MA 6V", Manufacturer="Nidec Copal Electronics"
SW2 SW3: library part CMP-0002150-2, "SWITCH TACTILE SPST-NO 0.05A 12V", CurrentRating_mA=50A, Manufacturer="Omron Electronic Components", Supplier Part Number 1=SW1020CT-ND
TP2 TP3 TP4 TP5 TP6 TP7 TP8 TP9 TP10 TP12 TP13 TP14 TP15 TP16 TP17 TP18 TP19 TP26 TP27 TP46: library part CMP-0078143-3, "TEST POINT.  No entry in BOM.", Manufacturer=N/A
TP11: library part CMP-0003825-1, "1mm Test Point, SMT", Manufacturer=Any
TP20: library part CMP-0086474-1, "PC Test Point, Loop Brass, Tin Plating 0.047\" (1.19mm) Hole Diameter Mounting Type", Manufacturer="Keystone Electronics"
U1: library part CMP-0079120-2, "4-A + 2.5-A + Two 1.5-A Buck Converters With Integrated Switches, RNF0026C (VQFN-HR-26)", Alternate Manufacturer="Texas Instruments", Alternate PartNumber=LP87524JRNFTQ1
U2: library part CMP-0860942-2, "XI6843ARQGALP, ALP0180A (BGA-180)", Alternate Manufacturer="Texas Instruments"
U3: library part CMP-0087172-1, "I/O Controller Interface IC USB to Dual UART bridge", Manufacturer="Silicon Labs"
U4: library part CMP-0035419-1, "Single Output High PSRR LDO, 200 mA, Fixed 3 V Output, 2.7 to 5.5 V Input, 5-pin SOT-23 (DBV), -40 to 85 degC, Green (RoHS & no Sb/Br)", Manufacturer="Texas Instruments", Rating=Catalog
U5: library part CMP-0067398-2, "Automotive Grade, 1.4V-Capable +/-0.5degC Temperature Sensor with Alert Function and I2C/SMBus, DRL0006A (SOT-OTHER-6)", Alternate Manufacturer="Texas Instruments"
U6: library part CMP-0087170-1, "8KB I2C SER EEPROM TSOT 23", Manufacturer="ON Semiconductor"
U7: library part CMP-0087171-1, "IMU ACCEL/GYRO/MAG I2C 32BIT", Manufacturer="Hillcrest Laboratories, Inc."
U8: library part CMP-0083675-2, "SimpleLink(TM) Bluetooth(R) 5 low energy Wireless MCU, RGZ0048A (VQFN-48)", Alternate Manufacturer="Texas Instruments", Alternate PartNumber=CC2642R1FRGZT, Operating Temperature Range="-40 to 85 C", Rating=#N/A
U9: library part CMP-0078466-1, "ULTRA LOW POWER, 16M-BIT [x 1/x 2/x 4] CMOS MXSMIO (SERIAL MULTI I/O) FLASH MEMORY, SON-8", Manufacturer="Macronix International Co., LTD", Supplier Part Number 1=1092-1178-1-ND
U10: library part CMP-0043349-1, "Low-Voltage 8-Bit I2C and SMBus I/O Expander, 1.65 to 5.5 V, -40 to 85 degC, 16-pin UQFN (RSV), Green (RoHS & no Sb/Br)", 5V Tolerant I/O=Yes, Manufacturer="Texas Instruments", Max Frequency(kHz)=400
U11: library part CMP-0050992-5, "1-Channel, 2:1 Analog Switch, DSF0006A (X2SON-6)", F @ Nom Voltage(Max)(Mhz)=150, Generic Part Number=SN74LVC1G3157, ICC @ Nom Voltage(Max)(mA)=0.01, Manufacturer="Texas Instruments", Operating Temperature Range="-40 to 85 C", Rating=Catalog, tpd @ Nom Voltage(Max)(ns)=2,1.2,0.8,0.3, Voltage(Nom)(V)=1.8,2.5,3.3,5
U12 U17: library part CMP-0065183-3, "Automotive Fault Protected CAN Transceiver With Flexible Data-Rate, DRB0008F (VSON-8)", Alternate Manufacturer="Texas Instruments", Alternate PartNumber=TCAN1042HGVDRBTQ1, Operating Temperature Range="-55 to 125 C", Rating=Automotive
U13: library part CMP-0067415-1, "10-Ohm Quad SPDT Analog Switch, RSV0016A (UQFN-16)", Alternate Manufacturer="Texas Instruments"
U14: library part CMP-0860038-1, "Automotive 4-Bit Bidirectional Voltage-Level Translator with Auto Direction Sensing and +/-15kV ESD, RUT0012A (UQFN-12)", Alternate Manufacturer="Texas Instruments", Operating Temperature Range="-40 to 125 C", Rating=Automotive
U15 U18: library part CMP-0074545-1, "Dual 10-ohm SPDT Analog Switch, RSE0010A (UQFN-10)", Alternate Manufacturer="Texas Instruments"
U16: library part CMP-0087998-2, "AND Gate IC 1 Channel  6-SON (1x1)", Digikey Part Number=296-30121-1-ND, Manufacturer="Texas Instruments", Max Supply Voltage=5.5V, Min Supply Voltage=1.65V, Mouser Part Number=595-SN74LVC1G11DSFR, Operating Temperature Range="-40°C to +125°C"
U19: library part CMP-0043358-3, "Dual In / Single Out Autoswitching Power Mux, 2.8 to 5.5 V, -40 to 85 degC, 8-pin SON (DRB), Green (RoHS & no Sb/Br)", IN1, IN2 Input Voltage(Max)(V)=5.5, IN1, IN2 Input Voltage(Min)(V)=2.8, IN1 Output Current(Max)(A)=1.25, Manufacturer="Texas Instruments"
Y1: library part CMP-0087164-1, "CRYSTAL 40.0000MHZ 8PF SMD", Frequency_Fixed=40MHz, Frequency Stability=15ppm, Load Capacitance=8pF, Manufacturer="Kyocera International Inc. Electronic Components"
Y2: library part CMP-0088076-1, "48MHz ±20ppm Crystal 7pF 50 Ohms 4-SMD, No Lead", Frequency_Fixed=48MHz, Frequency Tolerance=20ppm, Load Capacitance=7pF, Manufacturer=Kyocera
Y3 Y4: library part CMP-0088006-1, "CRYSTAL 32.768KHZ 4PF SMD", Frequency_Fixed=32.768kHz, Frequency Tolerance=20ppm, Load Capacitance=4pF, Manufacturer="Abracon LLC"
ZZ1: library part CMP-0003616-3
ZZ2: library part CMP-0077236-1
ZZ3: library part CMP-0077237-1
ZZ4 ZZ5.2: library part CMP-0077238-1
ZZ5.1: library part CMP-0077238-1, "Cut the thermal pad(Part Number#GPVOUS-0.125-AC-0816) for the shape and size of the inner surface of the heatsink(Part Number#160018120021) and paste it on the inner surface of the heatsink;"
